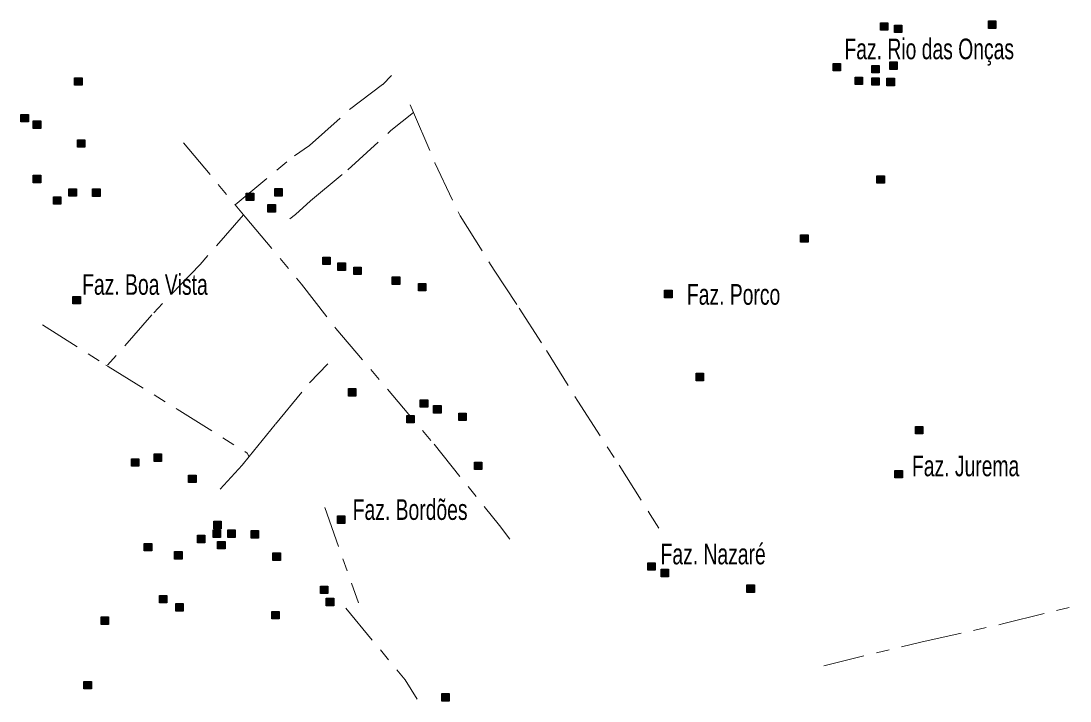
# Model space of a CAD drawing. Extents: x 445.4 to 500, y 8728.7 to 8784.
# Drawn here: x 463.95 to 472.09, y 8747.25 to 8752.52 of the extents above; entities that cross this region are included whole.
import ezdxf

# ---------------------------------------------------------------- set-up
doc = ezdxf.new("R2010")
doc.units = 0
doc.header["$LTSCALE"] = 0.064
doc.linetypes.add('DOT_DASHED', pattern=[7.7, 5, -1.2, 0.3, -1.2])
doc.layers.add('2', color=7, linetype='Continuous', lineweight=25)
doc.layers.add('22', color=7, linetype='DOT_DASHED', lineweight=13)
doc.layers.add('61', color=7, linetype='Continuous')

msp = doc.modelspace()

# ---------------------------------------------------------------- hatches: boundary and pattern name
at = {"layer": '2'}
for points in [[(470.6165, 8752.5024), (470.6745, 8752.5024), (470.6745, 8752.4444), (470.6165, 8752.4444)], [(470.7251, 8752.4843), (470.7831, 8752.4843), (470.7831, 8752.4263), (470.7251, 8752.4263)], [(471.4536, 8752.516), (471.5116, 8752.516), (471.5116, 8752.458), (471.4536, 8752.458)], [(470.2491, 8752.1869), (470.3071, 8752.1869), (470.3071, 8752.1289), (470.2491, 8752.1289)], [(470.5486, 8752.1719), (470.6066, 8752.1719), (470.6066, 8752.1139), (470.5486, 8752.1139)], [(470.6889, 8752.1991), (470.7469, 8752.1991), (470.7469, 8752.1411), (470.6889, 8752.1411)], [(464.3661, 8752.0768), (464.4241, 8752.0768), (464.4241, 8752.0188), (464.3661, 8752.0188)], [(470.4203, 8752.0813), (470.4783, 8752.0813), (470.4783, 8752.0233), (470.4203, 8752.0233)], [(470.5494, 8752.0759), (470.6074, 8752.0759), (470.6074, 8752.0179), (470.5494, 8752.0179)], [(470.6663, 8752.0723), (470.7243, 8752.0723), (470.7243, 8752.0143), (470.6663, 8752.0143)], [(463.9498, 8751.7916), (464.0078, 8751.7916), (464.0078, 8751.7336), (463.9498, 8751.7336)], [(464.0448, 8751.7418), (464.1028, 8751.7418), (464.1028, 8751.6838), (464.0448, 8751.6838)], [(464.3878, 8751.5962), (464.4458, 8751.5962), (464.4458, 8751.5382), (464.3878, 8751.5382)], [(464.0448, 8751.3207), (464.1028, 8751.3207), (464.1028, 8751.2627), (464.0448, 8751.2627)], [(470.5894, 8751.3162), (470.6474, 8751.3162), (470.6474, 8751.2582), (470.5894, 8751.2582)], [(464.3222, 8751.2156), (464.3802, 8751.2156), (464.3802, 8751.1576), (464.3222, 8751.1576)], [(464.5048, 8751.2149), (464.5628, 8751.2149), (464.5628, 8751.1569), (464.5048, 8751.1569)], [(465.6973, 8751.1818), (465.7553, 8751.1818), (465.7553, 8751.1238), (465.6973, 8751.1238)], [(465.9188, 8751.217), (465.9768, 8751.217), (465.9768, 8751.159), (465.9188, 8751.159)], [(464.2008, 8751.1535), (464.2588, 8751.1535), (464.2588, 8751.0955), (464.2008, 8751.0955)], [(465.8652, 8751.0934), (465.9232, 8751.0934), (465.9232, 8751.0354), (465.8652, 8751.0354)], [(469.9966, 8750.8589), (470.0546, 8750.8589), (470.0546, 8750.8009), (469.9966, 8750.8009)], [(466.2906, 8750.6859), (466.3486, 8750.6859), (466.3486, 8750.6279), (466.2906, 8750.6279)], [(466.4082, 8750.6406), (466.4662, 8750.6406), (466.4662, 8750.5826), (466.4082, 8750.5826)], [(466.5304, 8750.6089), (466.5884, 8750.6089), (466.5884, 8750.5509), (466.5304, 8750.5509)], [(466.8291, 8750.532), (466.8871, 8750.532), (466.8871, 8750.474), (466.8291, 8750.474)], [(467.0327, 8750.4822), (467.0907, 8750.4822), (467.0907, 8750.4242), (467.0327, 8750.4242)], [(468.9423, 8750.4288), (469.0003, 8750.4288), (469.0003, 8750.3708), (468.9423, 8750.3708)], [(464.3525, 8750.3808), (464.4105, 8750.3808), (464.4105, 8750.3228), (464.3525, 8750.3228)], [(469.1866, 8749.7859), (469.2446, 8749.7859), (469.2446, 8749.7279), (469.1866, 8749.7279)], [(466.4897, 8749.6672), (466.5477, 8749.6672), (466.5477, 8749.6092), (466.4897, 8749.6092)], [(467.0463, 8749.5812), (467.1043, 8749.5812), (467.1043, 8749.5232), (467.0463, 8749.5232)], [(467.1503, 8749.5359), (467.2083, 8749.5359), (467.2083, 8749.4779), (467.1503, 8749.4779)], [(466.9422, 8749.459), (467.0002, 8749.459), (467.0002, 8749.401), (466.9422, 8749.401)], [(467.3449, 8749.4771), (467.4029, 8749.4771), (467.4029, 8749.4191), (467.3449, 8749.4191)], [(470.888, 8749.3739), (470.946, 8749.3739), (470.946, 8749.3159), (470.888, 8749.3159)], [(464.8064, 8749.1239), (464.8644, 8749.1239), (464.8644, 8749.0659), (464.8064, 8749.0659)], [(464.9829, 8749.1602), (465.0409, 8749.1602), (465.0409, 8749.1022), (464.9829, 8749.1022)], [(467.4671, 8749.0968), (467.5251, 8749.0968), (467.5251, 8749.0388), (467.4671, 8749.0388)], [(465.2498, 8748.9972), (465.3078, 8748.9972), (465.3078, 8748.9392), (465.2498, 8748.9392)], [(470.7289, 8749.0335), (470.7869, 8749.0335), (470.7869, 8748.9755), (470.7289, 8748.9755)], [(465.4444, 8748.6395), (465.5024, 8748.6395), (465.5024, 8748.5815), (465.4444, 8748.5815)], [(466.4037, 8748.6803), (466.4617, 8748.6803), (466.4617, 8748.6223), (466.4037, 8748.6223)], [(465.4399, 8748.5716), (465.4979, 8748.5716), (465.4979, 8748.5136), (465.4399, 8748.5136)], [(465.553, 8748.5716), (465.611, 8748.5716), (465.611, 8748.5136), (465.553, 8748.5136)], [(465.734, 8748.5671), (465.792, 8748.5671), (465.792, 8748.5091), (465.734, 8748.5091)], [(465.3177, 8748.5308), (465.3757, 8748.5308), (465.3757, 8748.4728), (465.3177, 8748.4728)], [(465.4752, 8748.4827), (465.5332, 8748.4827), (465.5332, 8748.4247), (465.4752, 8748.4247)], [(464.9059, 8748.4675), (464.9639, 8748.4675), (464.9639, 8748.4095), (464.9059, 8748.4095)], [(465.1412, 8748.4041), (465.1992, 8748.4041), (465.1992, 8748.3461), (465.1412, 8748.3461)], [(465.9043, 8748.3936), (465.9623, 8748.3936), (465.9623, 8748.3356), (465.9043, 8748.3356)], [(468.811, 8748.3173), (468.869, 8748.3173), (468.869, 8748.2593), (468.811, 8748.2593)], [(468.9151, 8748.2675), (468.9731, 8748.2675), (468.9731, 8748.2095), (468.9151, 8748.2095)], [(469.5803, 8748.1452), (469.6383, 8748.1452), (469.6383, 8748.0872), (469.5803, 8748.0872)], [(465.0236, 8748.0645), (465.0816, 8748.0645), (465.0816, 8748.0065), (465.0236, 8748.0065)], [(466.2725, 8748.137), (466.3305, 8748.137), (466.3305, 8748.079), (466.2725, 8748.079)], [(465.1503, 8748.0011), (465.2083, 8748.0011), (465.2083, 8747.9431), (465.1503, 8747.9431)], [(466.3177, 8748.0419), (466.3757, 8748.0419), (466.3757, 8747.9839), (466.3177, 8747.9839)], [(465.8953, 8747.9399), (465.9533, 8747.9399), (465.9533, 8747.8819), (465.8953, 8747.8819)], [(464.5711, 8747.897), (464.6291, 8747.897), (464.6291, 8747.839), (464.5711, 8747.839)], [(464.4385, 8747.3972), (464.4965, 8747.3972), (464.4965, 8747.3392), (464.4385, 8747.3392)], [(467.2137, 8747.3039), (467.2717, 8747.3039), (467.2717, 8747.2459), (467.2137, 8747.2459)]]:
    msp.add_hatch(color=256, dxfattribs=at).paths.add_polyline_path(points)

# ---------------------------------------------------------------- linework, layer by layer
for points in [[(470.6165, 8752.5024), (470.6745, 8752.5024), (470.6745, 8752.4444), (470.6165, 8752.4444)], [(470.7251, 8752.4843), (470.7831, 8752.4843), (470.7831, 8752.4263), (470.7251, 8752.4263)], [(471.4536, 8752.516), (471.5116, 8752.516), (471.5116, 8752.458), (471.4536, 8752.458)], [(470.2491, 8752.1869), (470.3071, 8752.1869), (470.3071, 8752.1289), (470.2491, 8752.1289)], [(470.5486, 8752.1719), (470.6066, 8752.1719), (470.6066, 8752.1139), (470.5486, 8752.1139)], [(470.6889, 8752.1991), (470.7469, 8752.1991), (470.7469, 8752.1411), (470.6889, 8752.1411)], [(464.3661, 8752.0768), (464.4241, 8752.0768), (464.4241, 8752.0188), (464.3661, 8752.0188)], [(470.4203, 8752.0813), (470.4783, 8752.0813), (470.4783, 8752.0233), (470.4203, 8752.0233)], [(470.5494, 8752.0759), (470.6074, 8752.0759), (470.6074, 8752.0179), (470.5494, 8752.0179)], [(470.6663, 8752.0723), (470.7243, 8752.0723), (470.7243, 8752.0143), (470.6663, 8752.0143)], [(463.9498, 8751.7916), (464.0078, 8751.7916), (464.0078, 8751.7336), (463.9498, 8751.7336)], [(464.0448, 8751.7418), (464.1028, 8751.7418), (464.1028, 8751.6838), (464.0448, 8751.6838)], [(464.3878, 8751.5962), (464.4458, 8751.5962), (464.4458, 8751.5382), (464.3878, 8751.5382)], [(464.0448, 8751.3207), (464.1028, 8751.3207), (464.1028, 8751.2627), (464.0448, 8751.2627)], [(470.5894, 8751.3162), (470.6474, 8751.3162), (470.6474, 8751.2582), (470.5894, 8751.2582)], [(464.3222, 8751.2156), (464.3802, 8751.2156), (464.3802, 8751.1576), (464.3222, 8751.1576)], [(464.5048, 8751.2149), (464.5628, 8751.2149), (464.5628, 8751.1569), (464.5048, 8751.1569)], [(465.6973, 8751.1818), (465.7553, 8751.1818), (465.7553, 8751.1238), (465.6973, 8751.1238)], [(465.9188, 8751.217), (465.9768, 8751.217), (465.9768, 8751.159), (465.9188, 8751.159)], [(464.2008, 8751.1535), (464.2588, 8751.1535), (464.2588, 8751.0955), (464.2008, 8751.0955)], [(465.8652, 8751.0934), (465.9232, 8751.0934), (465.9232, 8751.0354), (465.8652, 8751.0354)], [(469.9966, 8750.8589), (470.0546, 8750.8589), (470.0546, 8750.8009), (469.9966, 8750.8009)], [(466.2906, 8750.6859), (466.3486, 8750.6859), (466.3486, 8750.6279), (466.2906, 8750.6279)], [(466.4082, 8750.6406), (466.4662, 8750.6406), (466.4662, 8750.5826), (466.4082, 8750.5826)], [(466.5304, 8750.6089), (466.5884, 8750.6089), (466.5884, 8750.5509), (466.5304, 8750.5509)], [(466.8291, 8750.532), (466.8871, 8750.532), (466.8871, 8750.474), (466.8291, 8750.474)], [(467.0327, 8750.4822), (467.0907, 8750.4822), (467.0907, 8750.4242), (467.0327, 8750.4242)], [(468.9423, 8750.4288), (469.0003, 8750.4288), (469.0003, 8750.3708), (468.9423, 8750.3708)], [(464.3525, 8750.3808), (464.4105, 8750.3808), (464.4105, 8750.3228), (464.3525, 8750.3228)], [(469.1866, 8749.7859), (469.2446, 8749.7859), (469.2446, 8749.7279), (469.1866, 8749.7279)], [(466.4897, 8749.6672), (466.5477, 8749.6672), (466.5477, 8749.6092), (466.4897, 8749.6092)], [(467.0463, 8749.5812), (467.1043, 8749.5812), (467.1043, 8749.5232), (467.0463, 8749.5232)], [(467.1503, 8749.5359), (467.2083, 8749.5359), (467.2083, 8749.4779), (467.1503, 8749.4779)], [(466.9422, 8749.459), (467.0002, 8749.459), (467.0002, 8749.401), (466.9422, 8749.401)], [(467.3449, 8749.4771), (467.4029, 8749.4771), (467.4029, 8749.4191), (467.3449, 8749.4191)], [(470.888, 8749.3739), (470.946, 8749.3739), (470.946, 8749.3159), (470.888, 8749.3159)], [(464.8064, 8749.1239), (464.8644, 8749.1239), (464.8644, 8749.0659), (464.8064, 8749.0659)], [(464.9829, 8749.1602), (465.0409, 8749.1602), (465.0409, 8749.1022), (464.9829, 8749.1022)], [(467.4671, 8749.0968), (467.5251, 8749.0968), (467.5251, 8749.0388), (467.4671, 8749.0388)], [(465.2498, 8748.9972), (465.3078, 8748.9972), (465.3078, 8748.9392), (465.2498, 8748.9392)], [(470.7289, 8749.0335), (470.7869, 8749.0335), (470.7869, 8748.9755), (470.7289, 8748.9755)], [(465.4444, 8748.6395), (465.5024, 8748.6395), (465.5024, 8748.5815), (465.4444, 8748.5815)], [(466.4037, 8748.6803), (466.4617, 8748.6803), (466.4617, 8748.6223), (466.4037, 8748.6223)], [(465.4399, 8748.5716), (465.4979, 8748.5716), (465.4979, 8748.5136), (465.4399, 8748.5136)], [(465.553, 8748.5716), (465.611, 8748.5716), (465.611, 8748.5136), (465.553, 8748.5136)], [(465.734, 8748.5671), (465.792, 8748.5671), (465.792, 8748.5091), (465.734, 8748.5091)], [(465.3177, 8748.5308), (465.3757, 8748.5308), (465.3757, 8748.4728), (465.3177, 8748.4728)], [(465.4752, 8748.4827), (465.5332, 8748.4827), (465.5332, 8748.4247), (465.4752, 8748.4247)], [(464.9059, 8748.4675), (464.9639, 8748.4675), (464.9639, 8748.4095), (464.9059, 8748.4095)], [(465.1412, 8748.4041), (465.1992, 8748.4041), (465.1992, 8748.3461), (465.1412, 8748.3461)], [(465.9043, 8748.3936), (465.9623, 8748.3936), (465.9623, 8748.3356), (465.9043, 8748.3356)], [(468.811, 8748.3173), (468.869, 8748.3173), (468.869, 8748.2593), (468.811, 8748.2593)], [(468.9151, 8748.2675), (468.9731, 8748.2675), (468.9731, 8748.2095), (468.9151, 8748.2095)], [(469.5803, 8748.1452), (469.6383, 8748.1452), (469.6383, 8748.0872), (469.5803, 8748.0872)], [(465.0236, 8748.0645), (465.0816, 8748.0645), (465.0816, 8748.0065), (465.0236, 8748.0065)], [(466.2725, 8748.137), (466.3305, 8748.137), (466.3305, 8748.079), (466.2725, 8748.079)], [(465.1503, 8748.0011), (465.2083, 8748.0011), (465.2083, 8747.9431), (465.1503, 8747.9431)], [(466.3177, 8748.0419), (466.3757, 8748.0419), (466.3757, 8747.9839), (466.3177, 8747.9839)], [(465.8953, 8747.9399), (465.9533, 8747.9399), (465.9533, 8747.8819), (465.8953, 8747.8819)], [(464.5711, 8747.897), (464.6291, 8747.897), (464.6291, 8747.839), (464.5711, 8747.839)], [(464.4385, 8747.3972), (464.4965, 8747.3972), (464.4965, 8747.3392), (464.4385, 8747.3392)], [(467.2137, 8747.3039), (467.2717, 8747.3039), (467.2717, 8747.2459), (467.2137, 8747.2459)]]:
    msp.add_lwpolyline(points, close=True, dxfattribs=at)
at = {"layer": '22'}
for p, q in [((466.9687, 8751.8666), (466.9947, 8751.8057)), ((464.1165, 8750.1614), (464.6166, 8749.8434)), ((466.3079, 8748.7448), (466.5667, 8748.0078))]:
    msp.add_line(p, q, dxfattribs=at)
for points in [[(465.6106, 8751.0923), (466.0702, 8751.4723), (466.187, 8751.5501), (466.4985, 8751.8301), (466.7555, 8752.0246), (466.8242, 8752.0939)], [(466.0346, 8750.9828), (466.0804, 8751.0162), (466.1961, 8751.1216), (466.4842, 8751.3627), (466.8191, 8751.6661), (466.9947, 8751.8057)], [(466.9947, 8751.8057), (467.1605, 8751.4179), (467.3552, 8751.0056), (467.62, 8750.5856), (467.8147, 8750.2901), (468.025, 8749.9634), (468.2692, 8749.5705), (468.5885, 8749.0727), (468.83, 8748.6916), (468.8961, 8748.5858)], [(465.2115, 8751.5721), (465.6106, 8751.0923), (465.6766, 8751.0131)], [(465.6766, 8751.0131), (465.3395, 8750.6288), (464.9657, 8750.2399), (464.6166, 8749.8434)], [(465.6766, 8751.0131), (465.6898, 8750.9972), (466.126, 8750.476), (466.3908, 8750.1338), (467.1542, 8749.2365), (467.6604, 8748.6065), (467.7404, 8748.5009)], [(465.7201, 8749.1396), (465.9236, 8749.3921), (466.1884, 8749.711), (466.3291, 8749.8597)], [(464.6076, 8749.8492), (464.6256, 8749.8376), (465.1604, 8749.5087), (465.7055, 8749.1665), (465.7201, 8749.1394)], [(465.4959, 8748.8881), (465.6666, 8749.0732), (465.7201, 8749.1396)], [(470.1774, 8747.5197), (470.9289, 8747.7017), (471.5746, 8747.8464), (472.4349, 8748.0596)], [(466.4688, 8747.9643), (466.9303, 8747.4107), (467.0237, 8747.2589)]]:
    msp.add_lwpolyline(points, dxfattribs=at)

# ---------------------------------------------------------------- texts
at = {"layer": '61', "width": 0.7}
for s, p in [('Faz. Rio das Onças', (470.3372, 8752.2196)), ('Faz. Boa Vista', (464.4244, 8750.3939)), ('Faz. Porco', (469.115, 8750.3169)), ('Faz. Jurema', (470.8608, 8748.9877)), ('Faz. Bordões', (466.523, 8748.6494)), ('Faz. Nazaré', (468.9108, 8748.3049))]:
    msp.add_text(s, height=0.16, dxfattribs=at).set_placement(p)

doc.saveas('drawing.dxf')
